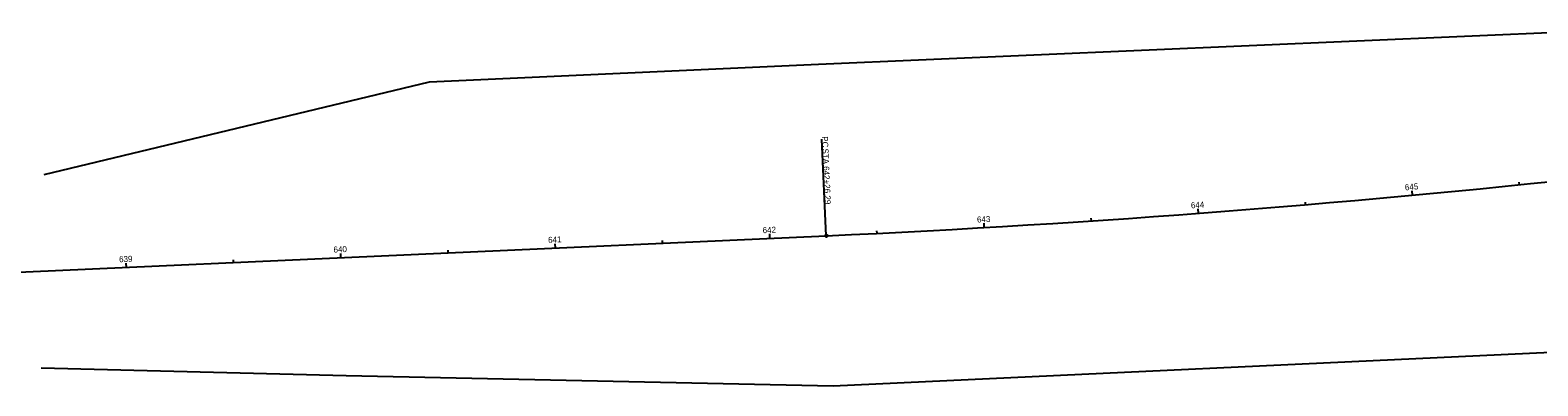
# Model space of a CAD drawing. Extents: x 1390087 to 1393932, y 303908 to 305061.
# Drawn here: x 1390986 to 1391688, y 304279 to 304444 of the extents above; entities that cross this region are included whole.
import ezdxf

# ---------------------------------------------------------------- set-up
doc = ezdxf.new("R2010")
doc.units = 0
for name, color, linetype in [('RW_X_CL', 7, 'Continuous'), ('RW_X_CL_100_Cardinal_Points', 7, 'Continuous'), ('RW_X_CL_100_Stations', 7, 'Continuous'), ('RW_X_Esmt_SH', 7, 'Continuous')]:
    doc.layers.add(name, color=color, linetype=linetype)

msp = doc.modelspace()

# ---------------------------------------------------------------- linework, layer by layer
at = {"layer": 'RW_X_CL'}
msp.add_line((1390089.1, 304291.23), (1391356.73, 304348.55), dxfattribs=at)
msp.add_line((1390089.1, 304291.23), (1391356.73, 304348.55), dxfattribs=at)
msp.add_arc((1391097.92, 310072.28), 5729.58, 272.589038, 280.105736, dxfattribs=at)
msp.add_arc((1391097.92, 310072.28), 5729.58, 272.589038, 280.105736, dxfattribs=at)
at = {"layer": 'RW_X_CL_100_Cardinal_Points'}
msp.add_line((1391356.73, 304348.55), (1391354.7, 304393.5), dxfattribs=at)
msp.add_circle((1391356.73, 304348.55), 0.6, dxfattribs=at)
at = {"layer": 'RW_X_CL_100_Stations'}
for p, q in [((1391679.53, 304372.3), (1391679.41, 304373.49)), ((1391629.76, 304367.44), (1391629.58, 304369.43)), ((1391530.12, 304359.02), (1391529.97, 304361.02)), ((1391579.96, 304363.01), (1391579.86, 304364.21)), ((1391430.34, 304352.35), (1391430.23, 304354.35)), ((1391480.25, 304355.47), (1391480.17, 304356.67)), ((1391280.52, 304345.1), (1391280.47, 304346.3)), ((1391330.47, 304347.36), (1391330.38, 304349.36)), ((1391380.42, 304349.67), (1391380.36, 304350.87)), ((1391130.67, 304338.33), (1391130.58, 304340.32)), ((1391180.62, 304340.59), (1391180.57, 304341.78)), ((1391230.57, 304342.84), (1391230.48, 304344.84)), ((1391030.78, 304333.81), (1391030.69, 304335.81)), ((1391080.73, 304336.07), (1391080.67, 304337.27))]:
    msp.add_line(p, q, dxfattribs=at)
at = {"layer": 'RW_X_Esmt_SH'}
for p, q in [((1391353.12, 304428.47), (1391718.69, 304444.31)), ((1391172.01, 304420.28), (1391353.12, 304428.47)), ((1390992.53, 304377.13), (1391172.01, 304420.28)), ((1391359.89, 304278.62), (1391745.01, 304296.64)), ((1390991.1, 304286.97), (1391133.16, 304283.38)), ((1391133.16, 304283.38), (1391359.89, 304278.62))]:
    msp.add_line(p, q, dxfattribs=at)

# ---------------------------------------------------------------- texts
at = {"layer": 'RW_X_CL_100_Cardinal_Points'}
for s, p in [('PC', (1391354.68, 304394.8)), (' STA. ', (1391354.89, 304390.2)), ('642+26.29', (1391355.31, 304380.89))]:
    msp.add_text(s, height=2.8, rotation=272.58904, dxfattribs=at).set_placement(p)
at = {"layer": 'RW_X_CL_100_Stations'}
for s, rotation, p in [('645', 5.32614, (1391626.34, 304369.63)), ('644', 4.32614, (1391526.66, 304361.27)), ('642', 2.58911, (1391327.15, 304349.71)), ('643', 3.32614, (1391427.01, 304354.66)), ('641', 2.58911, (1391227.24, 304345.2)), ('639', 2.58911, (1391027.44, 304336.16)), ('640', 2.58911, (1391127.3, 304340.68))]:
    msp.add_text(s, height=2.8, rotation=rotation, dxfattribs=at).set_placement(p)

doc.saveas('drawing.dxf')
